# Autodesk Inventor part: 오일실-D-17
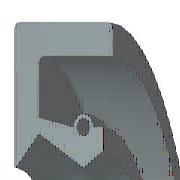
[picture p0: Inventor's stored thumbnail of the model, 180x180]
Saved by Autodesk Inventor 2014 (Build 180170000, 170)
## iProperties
IsCustomPart: 0
Company: 한국ATC센터
Created: 2014-12
Part Number: 오일실-D-17
Material: 고무
Description: 오일-실
Document SubType Name: Modeling
Standard: KS B 2804
Designer: KYOUNG IL JANG
Standards Organization: KS
Language: ko-KR
Size Designation: D - 17 30 8
Categories: <MemberInstance><Categories><Category DisplayName="샤프트 부품" InternalName="7f7aeb1f-a693-4053-b835-cee3144e0d98" Mnemonic="SHFT"><Category DisplayName="실링" Intern
Density: 0.93 g/cm^3
Mass: 2.05797 g
Surface Area: 29.3036 cm^2
Volume: 2.21288 cm^3
Appearance: 고무 - 파란색 - 버전 1.1
Author: KYOUNG IL JANG
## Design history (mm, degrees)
revolve "본체" stored, may be unused: angle "d17" = 90 deg
revolve "스프링1" stored, may be unused: angle "d18" = 90 deg
body "Solid1"
sketch "스케치1"
  geometry: L1 (0, 15)-(8, 15); L2 (8, 13.25)-(1.75, 13.25); L3 (1.75, 10.25)-(4.9, 8.5); L4 (4.9, 8.5)-(0, 8.5); L5 (0, 0)-(9.586, 0) reference; L6 (4.9, 8.5)-(6.3, 9.375); L7 (0, 18)-(0, -3) reference; L8 (-1.941, 0)-(11.507, 0) reference; L9 (4.2, 10.6)-(1.75, 11.21); L10 (1.75, 11.21)-(1.75, 13.25); L11 (0, 15)-(0, 8.588); L12 (4.9, 8.5)-(0, 8.5); L13 (1.75, 10.25)-(0.152, 8.528); L14 (8, 15)-(8, 13.25); L15 (5.6, 10.6)-(6.3, 10.6); L16 (6.3, 10.6)-(6.3, 9.375); C1 r 0.455 at (4.9, 10.6); A1 r 0.7 centre (4.9, 10.6) between (5.6, 10.6) and (4.2, 10.6); A2 r 0.088 centre (0.088, 8.588) between (0, 8.588) and (0.152, 8.528); 1 further point
  constraints: 28 end point, 5 horizontal alignment, 5 point on line, 4 point on circle, 4 vertical alignment, 3 centre point, 3 tangent, 2 collinear, 2 horizontal, 2 perpendicular, 1 coincident, 1 parallel
  dimensions: "d0" = 30 diameter of L1 L5 (= SD2); "d1" = 1.75 distance of L1.end L2.start (= SD); "d2" = 0.91 diameter of C1 (= SPDI); "d3" = 1.4 diameter of A1 (= SPDA); "d4" = 17 diameter of L3.end L5 (= NND); "d5" = 20.5 diameter of L3.start L5 (= TKDM); "d7" = 22.42 diameter of L9.end L5 (= TKDM + 0.24 x SWDT); "d8" = 1.75 distance between parallel lines of L11 L10 (= SD); "d9" = 4.9 distance from line of L11 C1.centre (= SPDST); "d10" = 21.2 diameter of C1.centre L5 (= HLDM); "d11" = 0.0875 radius of A2 (= 0.25 x LAB); "d12" = 6.3 distance between parallel lines of L11 L16 (= SDI); "d13" = 18.75 diameter of L6.end L5 (= ABDM); "d14" = 8 distance from line of L11 L1.end (= SWDT)
fillet "모깎기1" dims "d6" = 0.3 (= RR)
other parameters: "SD2" = 30 [user parameter; used in 1 equation term], "SWDT" = 8 [user parameter; used in 2 equation terms], "RR" = 0.3 [user parameter; used in 1 equation term], "SD" = 1.75 [user parameter; used in 2 equation terms], "NND" = 17 [user parameter; used in 1 equation term], "SPDA" = 1.4 [user parameter; used in 1 equation term], "SPDI" = 0.91 [user parameter; used in 1 equation term], "TKDM" = 20.5 [user parameter; used in 2 equation terms], "HLDM" = 21.2 [user parameter; used in 1 equation term], "ABDM" = 18.75 [user parameter; used in 1 equation term], "SDI" = 6.3 [user parameter; used in 1 equation term], "SPDST" = 4.9 [user parameter; used in 1 equation term], "LAB" = 0.35 [user parameter; used in 1 equation term], "d15" = 0, "d16" = 0, "d19" = 0
